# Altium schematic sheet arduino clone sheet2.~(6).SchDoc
size A; SheetNumber: 2; SheetTotal: 2
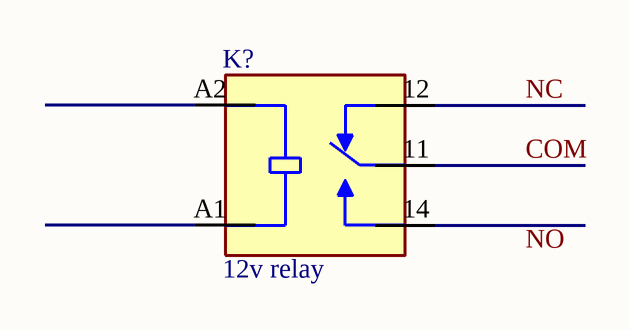
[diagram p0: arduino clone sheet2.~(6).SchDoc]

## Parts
K?  12v relay  [RELAY_833H-1C-S-12VDC]

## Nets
COM: K?.11(COM)
NC: K?.12(NC)

Not connected (* = marked no-connect by the designer): K? 14(NO) A1(COIL2) A2(COIL1)

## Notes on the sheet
- Labels drawn without touching a wire or pin: NO

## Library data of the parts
K? = 833H-1C-S-12VDC: 833H Series 10 A SPDT 12 VDC Through Hole Miniature Sugar Cube Power Relay; MF: Song Chuan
